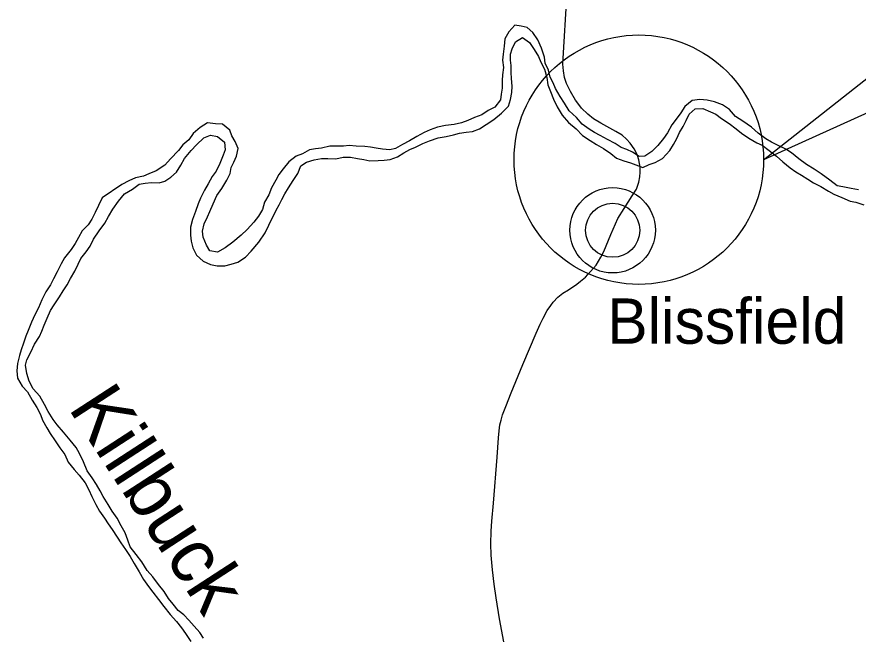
# Model space of a CAD drawing. Extents: x -6.3 to 34, y 0 to 22.
# Drawn here: x 2.2 to 3.205, y 17.695 to 18.433 of the extents above; entities that cross this region are included whole.
import ezdxf

# ---------------------------------------------------------------- set-up
doc = ezdxf.new("R2010")
doc.units = 0
for name, color, linetype in [('BR_P_Gen_Text', 7, 'Continuous'), ('Default', 7, 'Continuous'), ('GM_X_Major_River', 7, 'Continuous'), ('GM_X_Major_River_Text', 7, 'Continuous'), ('GM_X_State_Route', 7, 'Continuous'), ('GM_X_Unincorporated', 7, 'Continuous'), ('GM_X_Unincorporated_Location', 7, 'Continuous'), ('GM_X_Unincorporated_Text', 7, 'Continuous')]:
    doc.layers.add(name, color=color, linetype=linetype)

msp = doc.modelspace()

# ---------------------------------------------------------------- linework, layer by layer
at = {"layer": 'BR_P_Gen_Text'}
msp.add_lwpolyline([(3.9868, 18.9676), (3.9868, 18.6674), (3.0917, 18.2621)], close=True, dxfattribs=at)
at = {"layer": 'Default'}
msp.add_circle((2.9427, 18.2621), 0.149, dxfattribs=at)
at = {"layer": 'GM_X_Major_River'}
for points in [[(3.2049, 18.2262), (3.1961, 18.2275), (3.1863, 18.2295), (3.1795, 18.231), (3.1707, 18.2377), (3.1605, 18.2454), (3.1522, 18.2506), (3.1429, 18.2563), (3.1337, 18.2632), (3.1249, 18.2702), (3.1184, 18.2745), (3.109, 18.2792), (3.101, 18.283), (3.0942, 18.2871), (3.0851, 18.2938), (3.0771, 18.301), (3.0669, 18.3082), (3.0583, 18.3139), (3.051, 18.3222), (3.0427, 18.3276), (3.0331, 18.3314), (3.0243, 18.3334), (3.0155, 18.3342), (3.0062, 18.3328), (2.9976, 18.3258), (2.993, 18.3182), (2.9874, 18.3104), (2.9822, 18.3036), (2.9768, 18.2943), (2.9722, 18.2875), (2.9652, 18.2792), (2.9583, 18.2721), (2.95, 18.2664), (2.943, 18.2658), (2.9352, 18.2712), (2.9285, 18.2743), (2.9217, 18.2766), (2.9144, 18.2815), (2.9053, 18.2864), (2.8965, 18.2912), (2.8898, 18.2946), (2.8833, 18.2984), (2.8749, 18.3044), (2.8682, 18.3124), (2.8593, 18.3206), (2.8538, 18.3297), (2.8486, 18.3377), (2.8431, 18.347), (2.8405, 18.354), (2.8368, 18.3607), (2.8347, 18.369), (2.831, 18.3773), (2.8302, 18.3848), (2.8265, 18.3954), (2.8221, 18.4055), (2.8161, 18.414), (2.8093, 18.42), (2.8023, 18.4218), (2.7948, 18.4227), (2.7873, 18.4149), (2.7827, 18.4066), (2.7817, 18.3978), (2.7807, 18.3882), (2.7797, 18.3812), (2.781, 18.3721), (2.78, 18.3635), (2.7796, 18.3568), (2.7794, 18.3477), (2.7781, 18.3404), (2.7774, 18.3337), (2.7709, 18.3248), (2.7629, 18.3209), (2.7552, 18.3159), (2.7466, 18.3127), (2.7384, 18.3088), (2.7311, 18.3062), (2.7221, 18.3043), (2.712, 18.3029), (2.7024, 18.3011), (2.6936, 18.2979), (2.6864, 18.2945), (2.6776, 18.2898), (2.6688, 18.2848), (2.6603, 18.2801), (2.6523, 18.2754)], [(2.305, 18.1861), (2.3094, 18.1944), (2.3147, 18.203), (2.3212, 18.2126), (2.3286, 18.2212), (2.3379, 18.227), (2.3459, 18.233), (2.3532, 18.2341), (2.3607, 18.2349), (2.3698, 18.2344), (2.3765, 18.2365), (2.384, 18.2412), (2.3907, 18.2472), (2.3956, 18.2556), (2.4002, 18.2634), (2.4082, 18.273), (2.4144, 18.2798), (2.4231, 18.2884), (2.4311, 18.2913), (2.4397, 18.29), (2.4478, 18.2831), (2.4489, 18.274), (2.4463, 18.2675), (2.4422, 18.2576), (2.4381, 18.2485), (2.4332, 18.242), (2.4286, 18.2332), (2.424, 18.2259), (2.4194, 18.2163), (2.4163, 18.2092), (2.4132, 18.2001), (2.4097, 18.1905), (2.4074, 18.1814), (2.4072, 18.1721), (2.4082, 18.1646), (2.4101, 18.1568), (2.4143, 18.148), (2.4224, 18.1408), (2.4314, 18.1369), (2.4392, 18.1354), (2.4483, 18.1355), (2.4558, 18.1373), (2.4638, 18.1397), (2.4729, 18.1457), (2.4798, 18.153), (2.4891, 18.1637), (2.4965, 18.1749), (2.5009, 18.184), (2.5096, 18.2017), (2.5132, 18.2082), (2.5165, 18.2147), (2.5199, 18.2215), (2.5245, 18.2285), (2.5299, 18.2374), (2.5353, 18.2457), (2.5389, 18.2548), (2.5458, 18.259), (2.5549, 18.2621), (2.5637, 18.2637), (2.5712, 18.2635), (2.5808, 18.2633), (2.5896, 18.2652), (2.5984, 18.2652), (2.6067, 18.2637), (2.6142, 18.2622), (2.6215, 18.2607), (2.6313, 18.2613), (2.6386, 18.2616), (2.6458, 18.2624), (2.6546, 18.2655), (2.6621, 18.2702), (2.6694, 18.2744), (2.6761, 18.2771), (2.6849, 18.2813), (2.6929, 18.2847), (2.7032, 18.2881), (2.7128, 18.2897), (2.7213, 18.2918), (2.7286, 18.2937), (2.7364, 18.295), (2.7441, 18.2956), (2.7524, 18.2988), (2.7604, 18.3043), (2.7694, 18.3103), (2.7785, 18.3176), (2.787, 18.3262), (2.7893, 18.334), (2.791, 18.3423), (2.7913, 18.3498), (2.7907, 18.3592), (2.7904, 18.3664), (2.7901, 18.3745), (2.7893, 18.3812), (2.7895, 18.3882), (2.7915, 18.3947), (2.7954, 18.4028), (2.8039, 18.408), (2.8122, 18.4023), (2.8177, 18.3936), (2.8229, 18.3855), (2.8256, 18.3788)], [(2.8256, 18.3788), (2.83, 18.3703), (2.8329, 18.3602), (2.834, 18.3514), (2.8372, 18.3436), (2.8406, 18.3343), (2.8453, 18.3252), (2.8513, 18.3154), (2.8586, 18.3066), (2.8677, 18.2989), (2.8755, 18.2909), (2.8846, 18.2849), (2.8922, 18.2801), (2.9005, 18.2754), (2.9091, 18.2695), (2.9161, 18.2641), (2.9249, 18.2608), (2.9327, 18.2582), (2.9392, 18.2559), (2.9475, 18.2529), (2.955, 18.2563), (2.9622, 18.2586), (2.971, 18.2636), (2.9798, 18.273), (2.9842, 18.2803), (2.988, 18.2876), (2.9913, 18.2946), (2.9957, 18.3016), (2.999, 18.3089), (3.0029, 18.3165), (3.0098, 18.3227), (3.0189, 18.3233), (3.0283, 18.3192), (3.0347, 18.3164), (3.0415, 18.3115), (3.0506, 18.3053), (3.0589, 18.2989), (3.0654, 18.2937), (3.074, 18.2878), (3.0834, 18.2824), (3.0899, 18.2796), (3.0982, 18.2729), (3.107, 18.2662), (3.1146, 18.2597), (3.1234, 18.2525), (3.1302, 18.2476), (3.137, 18.2435), (3.1445, 18.2389), (3.1513, 18.2345), (3.1601, 18.2299), (3.1692, 18.2245), (3.1757, 18.2211), (3.185, 18.217), (3.1949, 18.2127), (3.2017, 18.2114), (3.2115, 18.2081)], [(2.6523, 18.2754), (2.6453, 18.274), (2.6364, 18.2745), (2.6292, 18.276), (2.6224, 18.277), (2.6154, 18.2778), (2.6051, 18.2782), (2.5968, 18.2792), (2.59, 18.2784), (2.5815, 18.2784), (2.5737, 18.2781), (2.5636, 18.2759), (2.5564, 18.2749), (2.5496, 18.2738), (2.5409, 18.2693), (2.5336, 18.2662), (2.5248, 18.2596), (2.5179, 18.251), (2.513, 18.2443), (2.5092, 18.2375), (2.504, 18.2284), (2.5007, 18.2203), (2.4958, 18.2112), (2.4933, 18.2026), (2.4884, 18.1946), (2.483, 18.1873), (2.475, 18.1787), (2.4678, 18.1719), (2.458, 18.1635), (2.4487, 18.157), (2.4397, 18.1518), (2.4306, 18.1533), (2.4264, 18.16), (2.4225, 18.1696), (2.4216, 18.1766), (2.4237, 18.1854), (2.4275, 18.1937), (2.4303, 18.2002), (2.4342, 18.2093), (2.4388, 18.2195), (2.4447, 18.2275), (2.4509, 18.2377), (2.4547, 18.2455), (2.456, 18.2528), (2.459, 18.2593), (2.4624, 18.2663), (2.4641, 18.2754), (2.4607, 18.2837), (2.4568, 18.2907), (2.4542, 18.2974), (2.4456, 18.3044), (2.437, 18.3048), (2.4277, 18.3061), (2.4189, 18.3006), (2.4107, 18.2935), (2.4053, 18.286), (2.3983, 18.28), (2.3929, 18.2729), (2.3836, 18.263), (2.3767, 18.2555), (2.3663, 18.2487), (2.3575, 18.2452), (2.3513, 18.2423), (2.3418, 18.2405), (2.3337, 18.2368), (2.3252, 18.2323), (2.302, 18.2166), (2.2974, 18.2073), (2.2933, 18.1992), (2.2897, 18.1909), (2.2853, 18.1841), (2.2778, 18.1773)], [(2.4229, 17.6904), (2.4185, 17.6971), (2.4117, 17.7046), (2.4052, 17.7118), (2.3992, 17.7185), (2.3927, 17.7237), (2.3867, 17.7309), (2.381, 17.7379), (2.3757, 17.7464), (2.369, 17.7544), (2.3622, 17.7637), (2.3554, 17.7712), (2.3491, 17.7815), (2.3426, 17.7903), (2.3353, 17.7994), (2.3327, 17.8074), (2.3292, 17.8165), (2.3245, 17.8245), (2.3198, 17.8338), (2.3138, 17.8421), (2.3089, 17.8501), (2.3031, 17.8596), (2.2994, 17.8666), (2.295, 17.8741), (2.29, 17.8821), (2.284, 17.8904), (2.2796, 17.9013), (2.2748, 17.9111), (2.2707, 17.9184), (2.2636, 17.9269), (2.2558, 17.9364), (2.248, 17.9452), (2.2435, 17.9519), (2.2375, 17.9613), (2.2331, 17.9698), (2.2273, 17.9794), (2.2195, 17.9884), (2.2145, 17.9977), (2.2119, 18.0065), (2.2105, 18.0166), (2.2121, 18.0231), (2.2167, 18.0322), (2.221, 18.0416), (2.2269, 18.0507), (2.23, 18.0572), (2.2326, 18.0645), (2.2362, 18.0728), (2.2403, 18.0819), (2.2446, 18.0887), (2.251, 18.0983), (2.2554, 18.1053), (2.26, 18.1126), (2.2641, 18.1202), (2.2693, 18.1288), (2.2731, 18.1371), (2.2762, 18.1441), (2.2826, 18.1519), (2.2875, 18.1587), (2.2916, 18.1673), (2.2983, 18.1772), (2.305, 18.1861)], [(2.2778, 18.1773), (2.2735, 18.1693), (2.2696, 18.162), (2.265, 18.155), (2.257, 18.1448), (2.2529, 18.1375), (2.248, 18.1281), (2.2437, 18.1196), (2.2403, 18.1125), (2.2347, 18.1042), (2.2298, 18.0948), (2.226, 18.0852), (2.2216, 18.0766), (2.2175, 18.0678), (2.2134, 18.0582), (2.2109, 18.0511), (2.2078, 18.0428), (2.205, 18.035), (2.203, 18.028), (2.2009, 18.0187), (2.2, 18.0098), (2.2008, 18.001), (2.2065, 17.9914), (2.2125, 17.9847), (2.2183, 17.9749), (2.2238, 17.9661), (2.2282, 17.9576), (2.2308, 17.9508), (2.2358, 17.9418), (2.2397, 17.9348), (2.2457, 17.9263), (2.2512, 17.9177), (2.2572, 17.91), (2.2612, 17.9007), (2.2685, 17.8921), (2.2742, 17.8852), (2.2815, 17.8761), (2.286, 17.8676), (2.2894, 17.8596), (2.2943, 17.8503), (2.2988, 17.842), (2.3048, 17.8337), (2.309, 17.827), (2.3137, 17.8203), (2.3199, 17.8112), (2.3241, 17.8045), (2.3299, 17.7962), (2.3351, 17.788), (2.3401, 17.7797), (2.3461, 17.7699), (2.3513, 17.7605), (2.357, 17.7523), (2.3623, 17.7453), (2.3693, 17.7365), (2.3756, 17.7282), (2.3831, 17.7187), (2.3907, 17.7104), (2.3967, 17.7027), (2.4014, 17.6959), (2.4079, 17.6864)]]:
    msp.add_lwpolyline(points, dxfattribs=at)
at = {"layer": 'GM_X_State_Route'}
for points in [[(2.8697, 18.3297), (2.8671, 18.3331), (2.8609, 18.3434), (2.8563, 18.3532), (2.8539, 18.3604), (2.8528, 18.3682), (2.8521, 18.3764), (2.8532, 18.3966), (2.856, 18.4429)], [(2.9253, 18.2037), (2.9349, 18.2188), (2.9397, 18.2269), (2.9425, 18.2354), (2.944, 18.2415), (2.9442, 18.2471), (2.9442, 18.2532), (2.9427, 18.2621), (2.9406, 18.2682), (2.9371, 18.2752), (2.9323, 18.2819), (2.928, 18.2865), (2.9226, 18.2913), (2.9154, 18.2958), (2.8972, 18.3056), (2.8886, 18.311), (2.8817, 18.3166), (2.8743, 18.3236), (2.8697, 18.3297)], [(2.9149, 18.1853), (2.9176, 18.1917), (2.9253, 18.2037)], [(2.7813, 17.6862), (2.7764, 17.7135), (2.7724, 17.7385), (2.77, 17.7548), (2.7679, 17.772), (2.7663, 17.7898), (2.7658, 17.803), (2.7663, 17.8182), (2.7671, 17.8303), (2.7692, 17.8516), (2.7737, 17.9069), (2.7751, 17.9299), (2.7759, 17.938), (2.7767, 17.9452), (2.7781, 17.951), (2.7799, 17.9574), (2.7837, 17.9673), (2.7903, 17.9836), (2.8043, 18.0175), (2.82, 18.0549), (2.8248, 18.0656), (2.8285, 18.0728), (2.8333, 18.082), (2.8375, 18.088), (2.8403, 18.0919), (2.8459, 18.0978), (2.8518, 18.1025), (2.8587, 18.1066), (2.8686, 18.1133), (2.8731, 18.1169), (2.8788, 18.1218), (2.8817, 18.125), (2.8916, 18.1362), (2.8973, 18.1455), (2.901, 18.1523), (2.9093, 18.1729), (2.9149, 18.1853)]]:
    msp.add_lwpolyline(points, dxfattribs=at)
at = {"layer": 'GM_X_Unincorporated'}
for radius in [0.051, 0.0323]:
    msp.add_circle((2.9114, 18.1778), radius, dxfattribs=at)
at = {"layer": 'GM_X_Unincorporated_Location'}
msp.add_line((2.9114, 18.1778), (2.9114, 18.1778), dxfattribs=at)

# ---------------------------------------------------------------- texts
at = {"layer": 'GM_X_Major_River_Text'}
msp.add_text('Killbuck', height=0.0649, rotation=302.9926, dxfattribs=at).set_placement((2.2606, 17.9655))
at = {"layer": 'GM_X_Unincorporated_Text'}
msp.add_text('Blissfield', height=0.05413, rotation=0, dxfattribs=at).set_placement((2.9049, 18.0422))

doc.saveas('drawing.dxf')
